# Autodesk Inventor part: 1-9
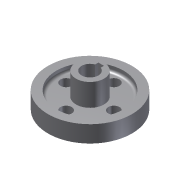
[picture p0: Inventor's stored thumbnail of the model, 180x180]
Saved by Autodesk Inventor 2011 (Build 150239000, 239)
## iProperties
Created: 2014-02
Part Number: 1-9
Document SubType Name: Modeling
Designer: Administrator
Density: 1 g/cm^3
Author: Administrator
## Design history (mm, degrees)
sketch "草图1"
  geometry: C1 r 15 at (0, 0); 1 further point
  constraints: 1 centre point, 1 coincident
  dimensions: "d0" = 30 diameter of C1
extrude "拉伸1" new body sketch "草图1" distance "d1" = 6; taper "d2" = 0 deg
sketch "草图2"
  geometry: C1 r 15 at (0, 0) reference; C2 r 12 at (0, 0)
  constraints: 1 centre point, 1 coincident
  dimensions: "d3" = 24 diameter of C2
extrude "拉伸2" cut sketch "草图2" distance "d4" = 2; taper "d5" = 0 deg
fillet "圆角1" dims "d6" = 1
sketch "草图3"
  geometry: C1 r 11 at (0, 0) reference; C2 r 5 at (0, 0)
  constraints: 1 centre point, 1 coincident
  dimensions: "d7" = 10 diameter of C2
extrude "拉伸3" join sketch "草图3" distance "d8" = 8; taper "d9" = 0 deg
sketch "草图4"
  geometry: L1 (-1, 4)-(1, 4); L2 (1, 4)-(1, 2.828); L3 (-1, 4)-(-1, 2.828); C1 r 5 at (0, 0) reference; A1 r 3 centre (0, 0) between (-1, 2.828) and (1, 2.828); 1 further point
  constraints: 6 end point, 2 point on circle, 1 centre point, 1 coincident, 1 horizontal, 1 midpoint, 1 parallel, 1 perpendicular, 1 vertical alignment
  dimensions: "d10" = 6 diameter of A1; "d11" = 2 distance of L1.start L1.end
extrude "拉伸4" cut sketch "草图4" stored distance "d12" = 12; taper "d13" = 0 deg
sketch "草图5"
  geometry: C1 r 2 at (-8.544, 0)
  constraints: 1 centre point
  dimensions: "d14" = 4 diameter of C1
extrude "拉伸5" cut sketch "草图5" stored distance "d15" = 12; taper "d16" = 0 deg
pattern_circular "环形阵列1" dims angle "d18" = 360 deg
node "实体1"
